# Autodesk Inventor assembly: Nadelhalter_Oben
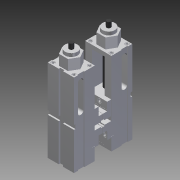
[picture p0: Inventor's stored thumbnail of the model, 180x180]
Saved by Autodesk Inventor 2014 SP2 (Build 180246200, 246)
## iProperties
Created: 2015-06
Part Number: Nadelhalter_Oben
Document SubType Name: Assembly
Designer: e_krauts
Sending System: SolidWorks 2011
Last Author: e_boekem
Author: e_krauts
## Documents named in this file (8)
- C:\SolidCAM_Temp\NADELHALTER_OBEN\DesignModel.iam
- C:\SolidCAM_Temp\NADELHALTER_OBEN\Backe20x40.ipt
- C:\SolidCAM_Temp\NADELHALTER_OBEN\Unterteil.ipt
- C:\SolidCAM_Temp\NADELHALTER_OBEN\Backe 40 x 20 ohne.ipt
- C:\SolidCAM_Temp\NADELHALTER_OBEN\Spindel.ipt
- C:\SolidCAM_Temp\NADELHALTER_OBEN\Schraubstock.iam
- Z:\VDW-Nachwuchsstiftung Intern\Mitarbeiter Ablage\Steffen Krauth\IVCAM\Nadelhalterung\DesignModel.ipt
- C:\SolidCAM_Temp\NADELHALTER_OBEN\Nadelhalterung-Oberteil_02.ipt
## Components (6 placed, 6 different names)
1. Backe20x40:1 — Passend:2, Fluchtend:1, Passend:6, Passend:7, Fluchtend:2, Fluchtend:3
2. Unterteil:1 — Passend:1, Passend:2, Passend:4, Passend:5, Fluchtend:1
3. Backe 40 x 20 ohne:1 — Passend:3, Passend:4, Passend:8, Fluchtend:4
4. Spindel:2 — Passend:1, Passend:3, Passend:5
5. Nadelhalterung-Oberteil_02:1 — Passend:6, Passend:7, Fluchtend:2, Passend:8, Passend:9, Passend:10
6. Schraubstock:1 [sub-assembly] — Fluchtend:3, Passend:9, Passend:10, Fluchtend:4
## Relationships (14: Mate 10, Flush 4)
- Passend:1 [Mate]: Unterteil:1 ↔ Spindel:2
- Passend:2 [Mate]: Backe20x40:1 ↔ Unterteil:1
- Passend:3 [Mate]: Backe 40 x 20 ohne:1 ↔ Spindel:2
- Passend:4 [Mate]: Unterteil:1 ↔ Backe 40 x 20 ohne:1
- Passend:5 [Mate]: Unterteil:1 ↔ Spindel:2
- Fluchtend:1 [Flush]: Backe20x40:1 ↔ Unterteil:1
- Passend:6 [Mate]: Backe20x40:1 ↔ Nadelhalterung-Oberteil_02:1
- Passend:7 [Mate]: Backe20x40:1 ↔ Nadelhalterung-Oberteil_02:1
- Fluchtend:2 [Flush]: Backe20x40:1 ↔ Nadelhalterung-Oberteil_02:1
- Passend:8 [Mate]: Backe 40 x 20 ohne:1 ↔ Nadelhalterung-Oberteil_02:1
- Fluchtend:3 [Flush]: Backe20x40:1 ↔ Schraubstock:1
- Passend:9 [Mate]: Nadelhalterung-Oberteil_02:1 ↔ Schraubstock:1
- Passend:10 [Mate]: Nadelhalterung-Oberteil_02:1 ↔ Schraubstock:1
- Fluchtend:4 [Flush]: Backe 40 x 20 ohne:1 ↔ Schraubstock:1
